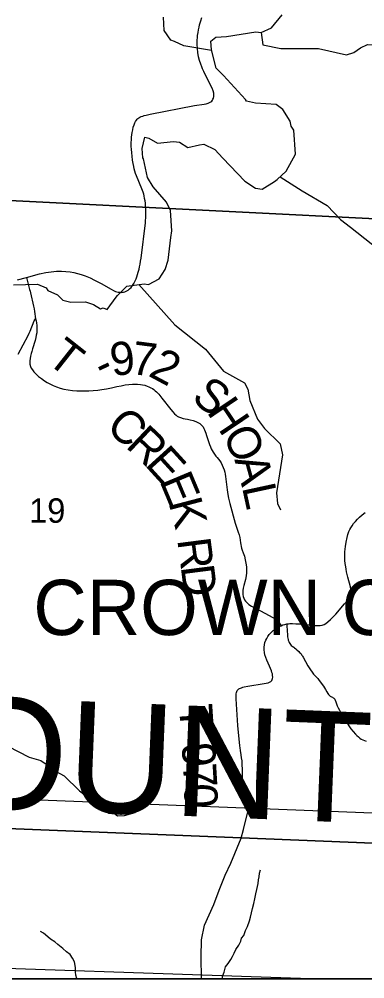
# Model space of a CAD drawing. Extents: x 0 to 34, y 0 to 22.
# Drawn here: x 25.347 to 25.938, y 14.1 to 15.745 of the extents above; entities that cross this region are included whole.
import ezdxf

# ---------------------------------------------------------------- set-up
doc = ezdxf.new("R2010")
doc.units = 0
for name, color, linetype in [('GM_X_Corporation_Text', 7, 'Continuous'), ('GM_X_County_Road', 7, 'Continuous'), ('GM_X_County_Text', 7, 'Continuous'), ('GM_X_Minor_River', 7, 'Continuous'), ('GM_X_Section', 7, 'Continuous'), ('GM_X_Section_Text', 7, 'Continuous'), ('GM_X_State_Route', 7, 'Continuous'), ('GM_X_State_Shield', 7, 'Continuous'), ('GM_X_Township_Road', 7, 'Continuous'), ('GM_X_Township_Road_Text', 7, 'Continuous'), ('SH_Cut_Line', 7, 'Continuous'), ('SH_Data', 7, 'Continuous')]:
    doc.layers.add(name, color=color, linetype=linetype)

msp = doc.modelspace()

# ---------------------------------------------------------------- linework, layer by layer
at = {"layer": 'GM_X_County_Road'}
msp.add_lwpolyline([(25.6591, 14.1), (25.6584, 14.1375), (25.6588, 14.1667), (25.664, 14.1922), (25.6799, 14.2276), (25.6893, 14.2519), (25.6995, 14.2777), (25.709, 14.2983), (25.7271, 14.3409)], dxfattribs=at)
at = {"layer": 'GM_X_County_Text'}
msp.add_lwpolyline([(23.8372, 20.6485), (23.8372, 14.4177), (24.4263, 14.3937), (25.7269, 14.3414), (26.0929, 14.3266), (26.1939, 14.3226), (26.568, 14.3076), (26.7502, 14.2997), (27.0716, 14.2873), (27.1862, 14.3829)], dxfattribs=at)
msp.add_lwpolyline([(23.8372, 14.4177), (23.8372, 14.1), (26.9036, 14.1), (26.9358, 14.1416), (26.9861, 14.1972), (27.0318, 14.2519), (27.0716, 14.2873), (26.7502, 14.2997), (26.568, 14.3076), (26.1939, 14.3226), (26.0929, 14.3266), (25.7269, 14.3414), (24.4263, 14.3937)], close=True, dxfattribs=at)
at = {"layer": 'GM_X_Minor_River'}
for points in [[(25.676, 15.6913), (25.6285, 15.6992), (25.6127, 15.7064), (25.6066, 15.709), (25.5949, 15.7253), (25.5941, 15.7481)], [(25.8197, 15.5135), (25.8169, 15.5549), (25.8124, 15.5613), (25.8105, 15.5701), (25.7984, 15.5902), (25.787, 15.5985), (25.7515, 15.6007), (25.736, 15.6045), (25.7341, 15.6075), (25.6966, 15.6484), (25.6841, 15.6609), (25.6758, 15.6921), (25.675, 15.7073), (25.6837, 15.7138), (25.7019, 15.715), (25.7517, 15.7231), (25.7612, 15.722), (25.779, 15.73), (25.7971, 15.7521)], [(25.7612, 15.722), (25.764, 15.7008), (25.7948, 15.6948), (25.8592, 15.6946), (25.907, 15.684), (25.9199, 15.6879), (25.9309, 15.6955), (25.943, 15.7016), (25.9775, 15.699), (26.0068, 15.6915), (26.033, 15.6801), (26.0679, 15.6586), (26.0926, 15.6522), (26.1268, 15.6279), (26.1385, 15.62), (26.1624, 15.6181), (26.2227, 15.6243), (26.3024, 15.6025), (26.3259, 15.5987), (26.3373, 15.5911), (26.3419, 15.5877)], [(25.6084, 15.3822), (25.6057, 15.4168), (25.5989, 15.4312), (25.5762, 15.4573), (25.5664, 15.4733), (25.5595, 15.5056), (25.5588, 15.5075), (25.5573, 15.5234), (25.5622, 15.5424), (25.5686, 15.5409), (25.5837, 15.5322), (25.6109, 15.5353), (25.6211, 15.5342), (25.6355, 15.5251), (25.6555, 15.5298), (25.6631, 15.5305), (25.6816, 15.5215), (25.6956, 15.5067), (25.7331, 15.4672), (25.7516, 15.4551), (25.763, 15.4536), (25.7841, 15.4666), (25.7886, 15.4701), (25.8038, 15.4845), (25.8197, 15.5135)], [(25.7936, 15.4748), (25.8315, 15.4504), (25.8742, 15.4255), (25.8969, 15.4016), (25.9139, 15.3885), (25.9741, 15.3407), (25.9921, 15.323), (26.0189, 15.3093), (26.1022, 15.2899), (26.1371, 15.2938), (26.1649, 15.3009), (26.2179, 15.303)], [(25.3371, 15.2895), (25.3783, 15.2908), (25.393, 15.2843), (25.3961, 15.2798), (25.4123, 15.2722), (25.4218, 15.2635), (25.4354, 15.2597), (25.4604, 15.2602), (25.474, 15.2556), (25.4864, 15.2485), (25.4906, 15.25), (25.4978, 15.2473), (25.5129, 15.2683), (25.5152, 15.2713), (25.531, 15.287), (25.5609, 15.2912), (25.5681, 15.2901), (25.5866, 15.2996), (25.5968, 15.316), (25.6017, 15.3316), (25.6062, 15.3704), (25.6084, 15.3822)], [(25.552, 15.29), (25.6132, 15.2207), (25.6657, 15.1792), (25.6967, 15.1418), (25.7323, 15.1213), (25.738, 15.1105), (25.7416, 15.091), (25.7546, 15.0594), (25.7666, 15.0431), (25.7938, 15.0172), (25.7974, 14.9981), (25.7875, 14.9331), (25.7892, 14.9148), (25.7941, 14.9036)], [(25.3273, 14.4985), (25.3643, 14.48), (25.384, 14.474), (25.4052, 14.46), (25.4093, 14.4562), (25.4241, 14.4482), (25.4502, 14.4221), (25.4944, 14.388), (25.5005, 14.3842), (25.5099, 14.3834), (25.5152, 14.3796), (25.527, 14.3797), (25.5455, 14.385), (25.5474, 14.3881)], [(25.6946, 14.1), (25.6956, 14.1059), (25.6975, 14.1112), (25.6987, 14.1158), (25.7, 14.1207), (25.7046, 14.126), (25.7089, 14.1331), (25.712, 14.138), (25.7151, 14.1437), (25.7175, 14.1501), (25.7229, 14.1576), (25.7261, 14.1644), (25.7277, 14.1694), (25.7316, 14.1742), (25.7344, 14.1826), (25.7379, 14.1894), (25.7411, 14.1992), (25.7427, 14.2057), (25.7443, 14.2129), (25.7463, 14.2208), (25.7484, 14.2288), (25.75, 14.2371), (25.7521, 14.2458), (25.7537, 14.253), (25.7549, 14.2584), (25.7557, 14.2633), (25.7566, 14.2694), (25.7574, 14.2747), (25.7583, 14.2811), (25.7599, 14.2868)], [(25.4457, 14.1), (25.4455, 14.1006), (25.4437, 14.1063), (25.4434, 14.112), (25.4431, 14.1196), (25.4418, 14.1292), (25.4384, 14.1353), (25.4344, 14.1414), (25.428, 14.1461), (25.4216, 14.1519), (25.4133, 14.1589), (25.4077, 14.1635), (25.4006, 14.1678), (25.3961, 14.1717), (25.3886, 14.1783), (25.3836, 14.1813)]]:
    msp.add_lwpolyline(points, dxfattribs=at)
at = {"layer": 'GM_X_Section'}
for points in [[(26.0395, 15.8225), (26.0137, 15.3999), (24.9883, 15.4512), (25.0112, 15.8778)], [(24.9883, 15.4512), (26.0137, 15.3999), (25.9993, 15.1693), (25.9925, 15.0615), (25.9851, 14.9419), (25.9779, 14.8211), (25.9703, 14.6911), (25.9621, 14.5516), (25.9518, 14.384), (24.9287, 14.4241)]]:
    msp.add_lwpolyline(points, close=True, dxfattribs=at)
at = {"layer": 'GM_X_State_Route'}
msp.add_lwpolyline([(25.3443, 15.298), (25.3593, 15.3021), (25.3818, 15.3082), (25.3928, 15.3105), (25.4017, 15.312), (25.4106, 15.3127), (25.4193, 15.3129), (25.4268, 15.3125), (25.4343, 15.3116), (25.4406, 15.3105), (25.4466, 15.309), (25.4532, 15.3071), (25.4601, 15.3047), (25.4682, 15.3014), (25.476, 15.2978), (25.4816, 15.2948), (25.4874, 15.2916), (25.5041, 15.2821), (25.5083, 15.28), (25.5118, 15.2784), (25.5143, 15.2777), (25.5165, 15.2771), (25.5193, 15.2767), (25.5213, 15.2766), (25.5235, 15.2768), (25.5255, 15.2771), (25.5278, 15.2777), (25.5303, 15.2787), (25.5332, 15.2804), (25.5357, 15.2824), (25.5384, 15.2852), (25.5409, 15.2883), (25.5433, 15.292), (25.5455, 15.2962), (25.5471, 15.2999), (25.5484, 15.3034), (25.5496, 15.307), (25.5508, 15.311), (25.5522, 15.3165), (25.5531, 15.3204), (25.5539, 15.3248), (25.5548, 15.3302), (25.5555, 15.3353), (25.563, 15.3958), (25.5634, 15.4001), (25.5636, 15.4044), (25.5637, 15.4082), (25.5639, 15.4121), (25.5637, 15.4166), (25.5635, 15.4208), (25.5632, 15.4253), (25.5629, 15.4294), (25.5623, 15.4336), (25.5616, 15.4374), (25.5607, 15.4419), (25.56, 15.445), (25.559, 15.4485), (25.5581, 15.4511), (25.557, 15.4539), (25.5476, 15.4764), (25.546, 15.4803), (25.5448, 15.4841), (25.5437, 15.4882), (25.5429, 15.4924), (25.542, 15.4973), (25.541, 15.5032), (25.5401, 15.51), (25.5395, 15.5157), (25.539, 15.5221), (25.5388, 15.5264), (25.5387, 15.5299), (25.5388, 15.5336), (25.5389, 15.5382), (25.5392, 15.5426), (25.5396, 15.5467), (25.5403, 15.5509), (25.5412, 15.5555), (25.5423, 15.5596), (25.5437, 15.564), (25.5449, 15.5672), (25.5462, 15.5697), (25.5476, 15.5718), (25.5489, 15.5734), (25.5501, 15.5746), (25.5516, 15.5758), (25.5536, 15.5769), (25.5559, 15.578), (25.5585, 15.5789), (25.5611, 15.5796), (25.564, 15.5803), (25.5713, 15.5818), (25.6468, 15.5967), (25.6637, 15.5994), (25.6672, 15.6), (25.6702, 15.6008), (25.6726, 15.6019), (25.6748, 15.6033), (25.6764, 15.6046), (25.6776, 15.6061), (25.6786, 15.6078), (25.6794, 15.6096), (25.68, 15.6122), (25.6802, 15.6148), (25.68, 15.618), (25.6791, 15.6223), (25.6775, 15.6264), (25.6648, 15.651), (25.6627, 15.6555), (25.6608, 15.6598), (25.6593, 15.6634), (25.6576, 15.6677), (25.6556, 15.674), (25.6541, 15.6805), (25.6527, 15.6877), (25.652, 15.6946), (25.6515, 15.7015), (25.6515, 15.7055), (25.6517, 15.7093), (25.6519, 15.7132), (25.6523, 15.7171), (25.6531, 15.722), (25.6539, 15.7267), (25.6548, 15.7311), (25.6558, 15.7354), (25.6567, 15.7388), (25.6577, 15.7421), (25.6598, 15.7475)], dxfattribs=at)
at = {"layer": 'GM_X_State_Shield'}
msp.add_lwpolyline([(25.1041, 14.1), (25.845, 14.1), (25.1054, 14.1249)], close=True, dxfattribs=at)
at = {"layer": 'GM_X_Township_Road'}
for points in [[(25.3593, 15.3021), (25.36, 15.2996), (25.3649, 15.2817), (25.3656, 15.2789), (25.3664, 15.2757), (25.3715, 15.2527), (25.3724, 15.2486), (25.3731, 15.2437), (25.3746, 15.2314), (25.3758, 15.2279), (25.3767, 15.2242), (25.3772, 15.22), (25.3774, 15.2158), (25.3773, 15.2117), (25.3769, 15.2073), (25.3762, 15.2032), (25.3754, 15.1995), (25.3741, 15.1943), (25.3697, 15.1798), (25.3684, 15.1753), (25.3674, 15.1716), (25.3664, 15.1675), (25.3656, 15.1632), (25.3651, 15.1595), (25.365, 15.1568), (25.3654, 15.1534), (25.3663, 15.1498), (25.3677, 15.1467), (25.3696, 15.1436), (25.3721, 15.1407), (25.3758, 15.1367), (25.38, 15.1327), (25.3852, 15.1288), (25.3905, 15.1249), (25.3948, 15.1223), (25.3993, 15.1198), (25.4052, 15.1169), (25.4111, 15.1145), (25.4172, 15.1124), (25.4236, 15.1108), (25.4308, 15.1095), (25.4383, 15.1085), (25.4455, 15.108), (25.4519, 15.1077), (25.4581, 15.1076), (25.4664, 15.1078), (25.4736, 15.1082), (25.4817, 15.109), (25.4884, 15.11), (25.4966, 15.1114), (25.505, 15.1131), (25.5142, 15.1152), (25.5216, 15.1167), (25.5284, 15.1179), (25.5347, 15.1187), (25.5409, 15.119), (25.5451, 15.1191), (25.5497, 15.119), (25.5543, 15.1185), (25.558, 15.1181), (25.5619, 15.1173), (25.5657, 15.1161), (25.5691, 15.1147), (25.5722, 15.1131), (25.5749, 15.1116), (25.5773, 15.11), (25.5798, 15.1079), (25.5818, 15.106), (25.584, 15.1039), (25.5858, 15.102), (25.5877, 15.0999), (25.5912, 15.0955), (25.6066, 15.0758), (25.6098, 15.0719), (25.613, 15.0683), (25.6154, 15.0661), (25.6172, 15.0647), (25.6196, 15.0632), (25.623, 15.0619), (25.6275, 15.0605), (25.6312, 15.0597), (25.635, 15.059), (25.6397, 15.0582), (25.6446, 15.0571), (25.6492, 15.0555), (25.6528, 15.0538), (25.656, 15.0517), (25.6583, 15.0498), (25.6602, 15.0479), (25.6617, 15.0459), (25.6631, 15.0435), (25.6643, 15.041), (25.6654, 15.0384), (25.6665, 15.0354), (25.6677, 15.0315), (25.6726, 15.0161), (25.6741, 15.012), (25.6755, 15.0087), (25.6773, 15.0054), (25.6789, 15.0026), (25.681, 14.9995), (25.6837, 14.9958), (25.6858, 14.9935), (25.6879, 14.991), (25.6903, 14.9877), (25.6925, 14.9843), (25.6943, 14.9805), (25.6963, 14.9762), (25.6977, 14.9724), (25.6988, 14.9687), (25.6996, 14.9648), (25.7002, 14.961), (25.7027, 14.9384), (25.7033, 14.9342), (25.704, 14.9299), (25.7053, 14.9238), (25.7075, 14.9147), (25.7168, 14.8812), (25.7201, 14.8707), (25.7218, 14.8658), (25.7232, 14.8612), (25.7243, 14.8562), (25.7257, 14.8474), (25.7262, 14.8444), (25.7268, 14.841), (25.7277, 14.8381), (25.7288, 14.8349), (25.7305, 14.83), (25.7323, 14.8247), (25.7339, 14.8183), (25.7351, 14.8126), (25.7359, 14.8061), (25.7361, 14.8005), (25.7358, 14.7956), (25.7353, 14.7907), (25.7341, 14.7846), (25.7313, 14.7739), (25.7301, 14.7694), (25.7295, 14.7654), (25.7295, 14.7621), (25.7297, 14.7586), (25.7303, 14.7555), (25.7314, 14.7522), (25.7326, 14.7495), (25.7343, 14.7471), (25.7365, 14.7448), (25.7402, 14.7418), (25.7444, 14.739), (25.7487, 14.7364), (25.7601, 14.7306), (25.7747, 14.7229), (25.7859, 14.7166), (25.7885, 14.7146), (25.7902, 14.7126), (25.7916, 14.7104), (25.7951, 14.7052)], [(25.3455, 15.1707), (25.3625, 15.2029), (25.3643, 15.2066), (25.3658, 15.21), (25.3727, 15.2277), (25.3735, 15.2293), (25.3746, 15.2314)], [(25.8049, 14.7082), (25.8076, 14.7086), (25.8103, 14.7088), (25.8146, 14.7088), (25.8205, 14.7087), (25.8267, 14.7085), (25.8328, 14.708), (25.8522, 14.7058), (25.8578, 14.7055), (25.8619, 14.7058), (25.8652, 14.7063), (25.8686, 14.7075), (25.872, 14.7092), (25.8754, 14.7117), (25.8798, 14.7161), (25.8889, 14.7252), (25.9039, 14.7425), (25.9099, 14.7493), (25.9124, 14.7528), (25.9139, 14.7556), (25.9146, 14.7581), (25.915, 14.7608), (25.915, 14.7642), (25.9147, 14.7676), (25.9139, 14.7717), (25.9095, 14.7887), (25.9082, 14.7932), (25.9073, 14.7975), (25.9064, 14.802), (25.9057, 14.8064), (25.905, 14.8116), (25.9044, 14.8171), (25.9042, 14.8219), (25.9041, 14.8268), (25.9043, 14.8321), (25.9047, 14.8367), (25.9052, 14.8408), (25.9064, 14.8484), (25.9081, 14.8562), (25.9096, 14.8616), (25.9112, 14.8667), (25.9127, 14.87), (25.9144, 14.8731), (25.9166, 14.8765), (25.9193, 14.8803), (25.9224, 14.8839), (25.9261, 14.8877), (25.9296, 14.8912), (25.934, 14.8952), (25.9392, 14.8995)], [(25.7951, 14.7052), (25.7983, 14.7066), (25.8015, 14.7076), (25.8049, 14.7082)], [(25.8049, 14.7082), (25.8051, 14.7053), (25.8061, 14.6889), (25.8064, 14.6862), (25.8067, 14.6838), (25.8071, 14.6818), (25.8075, 14.6804), (25.8083, 14.6781), (25.8091, 14.6763), (25.8101, 14.6746), (25.8113, 14.673), (25.8125, 14.6716), (25.814, 14.6703), (25.8169, 14.6682), (25.8184, 14.6671), (25.8203, 14.6656), (25.8222, 14.6639), (25.8253, 14.6611), (25.8269, 14.6596), (25.8284, 14.658), (25.8294, 14.6568), (25.8303, 14.6555), (25.8311, 14.6541), (25.8319, 14.6528), (25.8327, 14.6513), (25.8411, 14.6365), (25.8431, 14.6333), (25.8455, 14.6297), (25.8481, 14.6258), (25.8509, 14.6222), (25.8578, 14.6145), (25.8601, 14.6116), (25.8626, 14.6084), (25.8653, 14.6047), (25.8677, 14.6014), (25.8695, 14.5986), (25.8712, 14.5958), (25.8734, 14.5917), (25.875, 14.5892), (25.8764, 14.5874), (25.8775, 14.5861), (25.8784, 14.5852), (25.8793, 14.5845), (25.8803, 14.5839), (25.8817, 14.5833), (25.8833, 14.5825), (25.8845, 14.5817), (25.8855, 14.5811), (25.8863, 14.5801), (25.8869, 14.5792), (25.8875, 14.5777), (25.8886, 14.5749), (25.89, 14.5714), (25.8914, 14.568), (25.893, 14.5647), (25.8949, 14.5606), (25.8978, 14.5549), (25.9112, 14.5334), (25.9148, 14.5283), (25.9226, 14.5191), (25.925, 14.5168), (25.9276, 14.5146), (25.9302, 14.5124), (25.9324, 14.511), (25.935, 14.5095), (25.9379, 14.5082), (25.9408, 14.5072)], [(25.7271, 14.3409), (25.7307, 14.3558), (25.738, 14.3863), (25.7387, 14.3909), (25.7392, 14.3954), (25.7394, 14.3991), (25.7393, 14.402), (25.7391, 14.4045), (25.7385, 14.4071), (25.7376, 14.4096), (25.7365, 14.4127), (25.7342, 14.4181), (25.7327, 14.4218), (25.7314, 14.4249), (25.7305, 14.428), (25.7299, 14.4307), (25.7294, 14.4338), (25.7292, 14.4377), (25.7291, 14.4591), (25.7288, 14.4669), (25.7283, 14.4734), (25.7277, 14.479), (25.7268, 14.4838), (25.7256, 14.4915), (25.725, 14.4958), (25.7246, 14.4996), (25.7211, 14.534), (25.7183, 14.5798), (25.7182, 14.5831), (25.7182, 14.5859), (25.7184, 14.5886), (25.7187, 14.5907), (25.7192, 14.5924), (25.7201, 14.5942), (25.7212, 14.5956), (25.7226, 14.5968), (25.7242, 14.5976), (25.7258, 14.5983), (25.7277, 14.599), (25.7295, 14.5997), (25.732, 14.6003), (25.7384, 14.6015), (25.766, 14.606), (25.7698, 14.6067), (25.7728, 14.6075), (25.7754, 14.6084), (25.7774, 14.6096), (25.7791, 14.6113), (25.78, 14.6128), (25.7806, 14.615), (25.7808, 14.6173), (25.7806, 14.6198), (25.7803, 14.6226), (25.7796, 14.6253), (25.7788, 14.6279), (25.7753, 14.6361), (25.7706, 14.6464), (25.7688, 14.6508), (25.7675, 14.6553), (25.7667, 14.6594), (25.7662, 14.664), (25.7662, 14.6682), (25.7666, 14.6725), (25.7676, 14.6763), (25.7691, 14.6802), (25.7707, 14.6836), (25.7726, 14.687), (25.775, 14.6902), (25.7782, 14.6938), (25.7818, 14.6969), (25.7854, 14.6996), (25.7898, 14.7025), (25.7927, 14.704), (25.7951, 14.7052)]]:
    msp.add_lwpolyline(points, dxfattribs=at)
at = {"layer": 'SH_Cut_Line'}
msp.add_lwpolyline([(23.8372, 20.9), (23.8372, 14.4177), (24.4263, 14.3937), (25.7269, 14.3414), (26.0929, 14.3266), (26.1939, 14.3226), (26.568, 14.3076), (26.7502, 14.2997), (27.0716, 14.2873), (27.1862, 14.3829)], dxfattribs=at)
msp.add_lwpolyline([(23.8372, 14.4177), (23.8372, 14.1), (26.9036, 14.1), (26.9358, 14.1416), (26.9861, 14.1972), (27.0318, 14.2519), (27.0716, 14.2873), (26.7502, 14.2997), (26.568, 14.3076), (26.1939, 14.3226), (26.0929, 14.3266), (25.7269, 14.3414), (24.4263, 14.3937)], close=True, dxfattribs=at)
at = {"layer": 'SH_Data'}
msp.add_lwpolyline([(23.8372, 20.9), (30.6372, 20.9), (30.6372, 14.1), (23.8372, 14.1)], close=True, dxfattribs=at)

# ---------------------------------------------------------------- texts
at = {"layer": 'GM_X_Corporation_Text'}
msp.add_text('CROWN CITY', height=0.0947, rotation=0, dxfattribs=at).set_placement((25.3712, 14.6892))
at = {"layer": 'GM_X_County_Text'}
msp.add_text('GALLIA COUNTY', height=0.189394, rotation=357.6921, dxfattribs=at).set_placement((24.0901, 14.4413))
at = {"layer": 'GM_X_Section_Text'}
msp.add_text('19', height=0.04186, rotation=0, dxfattribs=at).set_placement((25.3638, 14.8817))
at = {"layer": 'GM_X_Township_Road_Text'}
for s, rotation, p in [('T', 321.6934, (25.3917, 15.158)), ('9', 7.2194, (25.5061, 15.1328)), ('7', 352.6564, (25.5368, 15.1371)), ('2', 331.7858, (25.566, 15.1344)), ('-', 25.1589, (25.4897, 15.1242)), ('S', 322.4849, (25.6397, 15.092)), ('H', 304.0114, (25.6668, 15.0721)), ('C', 317.6545, (25.4932, 15.0435)), ('R', 316.5581, (25.5275, 15.0123)), ('O', 296.3696, (25.6938, 15.0324)), ('E', 312.2838, (25.5606, 14.981)), ('A', 285.4495, (25.715, 14.9903)), ('E', 292.7214, (25.5864, 14.9539)), ('L', 282.2253, (25.7281, 14.9429)), ('K', 284.6879, (25.6022, 14.9167)), ('R', 277.3579, (25.6174, 14.8529)), ('D', 277.2942, (25.6233, 14.8067)), ('T', 273.8943, (25.6204, 14.569)), ('-', 273.8746, (25.6233, 14.5266)), ('9', 273.7288, (25.6249, 14.5034)), ('7', 273.3168, (25.6271, 14.4686)), ('0', 271.6968, (25.6291, 14.4341))]:
    msp.add_text(s, height=0.0568, rotation=rotation, dxfattribs=at).set_placement(p)

doc.saveas('drawing.dxf')
